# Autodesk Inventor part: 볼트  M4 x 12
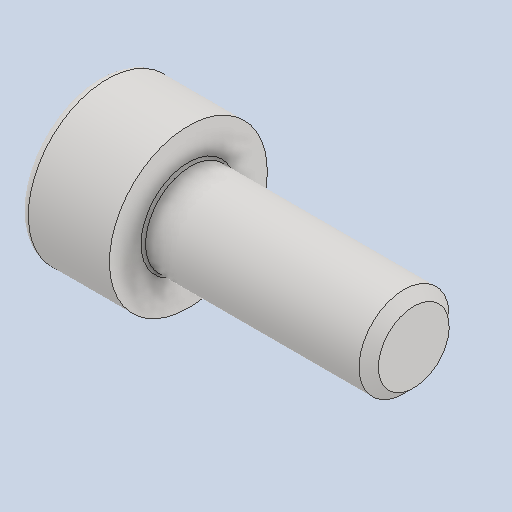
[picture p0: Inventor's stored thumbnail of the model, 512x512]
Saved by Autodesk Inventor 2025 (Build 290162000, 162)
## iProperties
Created: 2024-08
Part Number: 볼트  M4 x 12
Material: 스테인리스강
Description: 6각머리 태핑 나사
Document SubType Name: Modeling
Designer: Administrator
Density: 8.08 g/cm^3
Appearance: 기본값
Author: jhkim
Sending System: Autodesk Inventor 2025
Preprocessor: ST-DEVELOPER v20
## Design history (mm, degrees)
feature "Solid1"
node "솔리드1"
